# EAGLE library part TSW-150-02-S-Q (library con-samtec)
THROUGH-HOLE .025" SQ POST HEADER Source: Samtec TSW.pdf
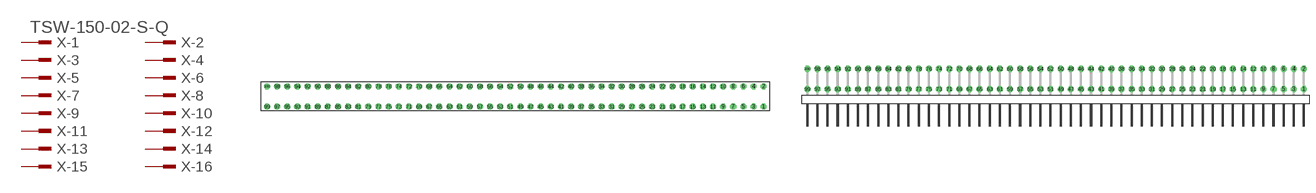
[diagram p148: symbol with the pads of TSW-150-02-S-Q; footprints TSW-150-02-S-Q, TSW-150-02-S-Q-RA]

Designator prefix X; gates -1=MPINV -2=MPIN -3=MPIN -4=MPIN -5=MPIN -6=MPIN -7=MPIN -8=MPIN -9=MPIN -10=MPIN -11=MPIN -12=MPIN -13=MPIN -14=MPIN -15=MPIN -16=MPIN -17=MPIN -18=MPIN -19=MPIN -20=MPIN -21=MPIN -22=MPIN -23=MPIN -24=MPIN -25=MPIN -26=MPIN -27=MPIN -28=MPIN -29=MPIN -30=MPIN -31=MPIN -32=MPIN -33=MPIN -34=MPIN -35=MPIN -36=MPIN -37=MPIN -38=MPIN -39=MPIN -40=MPIN -41=MPIN -42=MPIN -43=MPIN -44=MPIN -45=MPIN -46=MPIN -47=MPIN -48=MPIN -49=MPIN -50=MPIN -51=MPIN -52=MPIN -53=MPIN -54=MPIN -55=MPIN -56=MPIN -57=MPIN -58=MPIN -59=MPIN -60=MPIN -61=MPIN -62=MPIN -63=MPIN -64=MPIN -65=MPIN -66=MPIN -67=MPIN -68=MPIN -69=MPIN -70=MPIN -71=MPIN -72=MPIN -73=MPIN -74=MPIN -75=MPIN -76=MPIN -77=MPIN -78=MPIN -79=MPIN -80=MPIN -81=MPIN -82=MPIN -83=MPIN -84=MPIN -85=MPIN -86=MPIN -87=MPIN -88=MPIN -89=MPIN -90=MPIN -91=MPIN -92=MPIN -93=MPIN -94=MPIN -95=MPIN -96=MPIN -97=MPIN -98=MPIN -99=MPIN -100=MPIN

## TSW-150-02-S-Q (OC_FARNELL: unknown; OC_NEWARK: unknown)  [TSW-150-02-S-Q]
1  -1:1  pas
2  -2:1  pas
3  -3:1  pas
4  -4:1  pas
5  -5:1  pas
6  -6:1  pas
7  -7:1  pas
8  -8:1  pas
9  -9:1  pas
10  -10:1  pas
11  -11:1  pas
12  -12:1  pas
13  -13:1  pas
14  -14:1  pas
15  -15:1  pas
16  -16:1  pas
17  -17:1  pas
18  -18:1  pas
19  -19:1  pas
20  -20:1  pas
21  -21:1  pas
22  -22:1  pas
23  -23:1  pas
24  -24:1  pas
25  -25:1  pas
26  -26:1  pas
27  -27:1  pas
28  -28:1  pas
29  -29:1  pas
30  -30:1  pas
31  -31:1  pas
32  -32:1  pas
33  -33:1  pas
34  -34:1  pas
35  -35:1  pas
36  -36:1  pas
37  -37:1  pas
38  -38:1  pas
39  -39:1  pas
40  -40:1  pas
41  -41:1  pas
42  -42:1  pas
43  -43:1  pas
44  -44:1  pas
45  -45:1  pas
46  -46:1  pas
47  -47:1  pas
48  -48:1  pas
49  -49:1  pas
50  -50:1  pas
51  -51:1  pas
52  -52:1  pas
53  -53:1  pas
54  -54:1  pas
55  -55:1  pas
56  -56:1  pas
57  -57:1  pas
58  -58:1  pas
59  -59:1  pas
60  -60:1  pas
61  -61:1  pas
62  -62:1  pas
63  -63:1  pas
64  -64:1  pas
65  -65:1  pas
66  -66:1  pas
67  -67:1  pas
68  -68:1  pas
69  -69:1  pas
70  -70:1  pas
71  -71:1  pas
72  -72:1  pas
73  -73:1  pas
74  -74:1  pas
75  -75:1  pas
76  -76:1  pas
77  -77:1  pas
78  -78:1  pas
79  -79:1  pas
80  -80:1  pas
81  -81:1  pas
82  -82:1  pas
83  -83:1  pas
84  -84:1  pas
85  -85:1  pas
86  -86:1  pas
87  -87:1  pas
88  -88:1  pas
89  -89:1  pas
90  -90:1  pas
91  -91:1  pas
92  -92:1  pas
93  -93:1  pas
94  -94:1  pas
95  -95:1  pas
96  -96:1  pas
97  -97:1  pas
98  -98:1  pas
99  -99:1  pas
100  -100:1  pas

## TSW-150-02-S-Q-RA (OC_FARNELL: unknown; OC_NEWARK: unknown)  [TSW-150-02-S-Q-RA]
Pads as for TSW-150-02-S-Q

## Footprint TSW-150-02-S-Q (pad centres in mm)
THROUGH-HOLE .025" SQ POST HEADER Source: Samtec TSW.pdf
drill 1 pad 1.5 octagon: 1 62.23,-2.54; 2 62.23,2.54; 3 59.69,-2.54; 4 59.69,2.54; 5 57.15,-2.54; 6 57.15,2.54; 7 54.61,-2.54; 8 54.61,2.54; 9 52.07,-2.54; 10 52.07,2.54; 11 49.53,-2.54; 12 49.53,2.54; 13 46.99,-2.54; 14 46.99,2.54; 15 44.45,-2.54; 16 44.45,2.54; 17 41.91,-2.54; 18 41.91,2.54; 19 39.37,-2.54; 20 39.37,2.54; 21 36.83,-2.54; 22 36.83,2.54; 23 34.29,-2.54; 24 34.29,2.54; 25 31.75,-2.54; 26 31.75,2.54; 27 29.21,-2.54; 28 29.21,2.54; 29 26.67,-2.54; 30 26.67,2.54; 31 24.13,-2.54; 32 24.13,2.54; 33 21.59,-2.54; 34 21.59,2.54; 35 19.05,-2.54; 36 19.05,2.54; 37 16.51,-2.54; 38 16.51,2.54; 39 13.97,-2.54; 40 13.97,2.54; 41 11.43,-2.54; 42 11.43,2.54; 43 8.89,-2.54; 44 8.89,2.54; 45 6.35,-2.54; 46 6.35,2.54; 47 3.81,-2.54; 48 3.81,2.54; 49 1.27,-2.54; 50 1.27,2.54; 51 -1.27,-2.54; 52 -1.27,2.54; 53 -3.81,-2.54; 54 -3.81,2.54; 55 -6.35,-2.54; 56 -6.35,2.54; 57 -8.89,-2.54; 58 -8.89,2.54; 59 -11.43,-2.54; 60 -11.43,2.54; 61 -13.97,-2.54; 62 -13.97,2.54; 63 -16.51,-2.54; 64 -16.51,2.54; 65 -19.05,-2.54; 66 -19.05,2.54; 67 -21.59,-2.54; 68 -21.59,2.54; 69 -24.13,-2.54; 70 -24.13,2.54; 71 -26.67,-2.54; 72 -26.67,2.54; 73 -29.21,-2.54; 74 -29.21,2.54; 75 -31.75,-2.54; 76 -31.75,2.54; 77 -34.29,-2.54; 78 -34.29,2.54; 79 -36.83,-2.54; 80 -36.83,2.54; 81 -39.37,-2.54; 82 -39.37,2.54; 83 -41.91,-2.54; 84 -41.91,2.54; 85 -44.45,-2.54; 86 -44.45,2.54; 87 -46.99,-2.54; 88 -46.99,2.54; 89 -49.53,-2.54; 90 -49.53,2.54; 91 -52.07,-2.54; 92 -52.07,2.54; 93 -54.61,-2.54; 94 -54.61,2.54; 95 -57.15,-2.54; 96 -57.15,2.54; 97 -59.69,-2.54; 98 -59.69,2.54; 99 -62.23,-2.54; 100 -62.23,2.54

## Footprint TSW-150-02-S-Q-RA (pad centres in mm)
THROUGH-HOLE .025" SQ POST HEADER Source: Samtec TSW.pdf
drill 1 pad 1.5 octagon: 1 62.23,1.524; 2 62.23,6.604; 3 59.69,1.524; 4 59.69,6.604; 5 57.15,1.524; 6 57.15,6.604; 7 54.61,1.524; 8 54.61,6.604; 9 52.07,1.524; 10 52.07,6.604; 11 49.53,1.524; 12 49.53,6.604; 13 46.99,1.524; 14 46.99,6.604; 15 44.45,1.524; 16 44.45,6.604; 17 41.91,1.524; 18 41.91,6.604; 19 39.37,1.524; 20 39.37,6.604; 21 36.83,1.524; 22 36.83,6.604; 23 34.29,1.524; 24 34.29,6.604; 25 31.75,1.524; 26 31.75,6.604; 27 29.21,1.524; 28 29.21,6.604; 29 26.67,1.524; 30 26.67,6.604; 31 24.13,1.524; 32 24.13,6.604; 33 21.59,1.524; 34 21.59,6.604; 35 19.05,1.524; 36 19.05,6.604; 37 16.51,1.524; 38 16.51,6.604; 39 13.97,1.524; 40 13.97,6.604; 41 11.43,1.524; 42 11.43,6.604; 43 8.89,1.524; 44 8.89,6.604; 45 6.35,1.524; 46 6.35,6.604; 47 3.81,1.524; 48 3.81,6.604; 49 1.27,1.524; 50 1.27,6.604; 51 -1.27,1.524; 52 -1.27,6.604; 53 -3.81,1.524; 54 -3.81,6.604; 55 -6.35,1.524; 56 -6.35,6.604; 57 -8.89,1.524; 58 -8.89,6.604; 59 -11.43,1.524; 60 -11.43,6.604; 61 -13.97,1.524; 62 -13.97,6.604; 63 -16.51,1.524; 64 -16.51,6.604; 65 -19.05,1.524; 66 -19.05,6.604; 67 -21.59,1.524; 68 -21.59,6.604; 69 -24.13,1.524; 70 -24.13,6.604; 71 -26.67,1.524; 72 -26.67,6.604; 73 -29.21,1.524; 74 -29.21,6.604; 75 -31.75,1.524; 76 -31.75,6.604; 77 -34.29,1.524; 78 -34.29,6.604; 79 -36.83,1.524; 80 -36.83,6.604; 81 -39.37,1.524; 82 -39.37,6.604; 83 -41.91,1.524; 84 -41.91,6.604; 85 -44.45,1.524; 86 -44.45,6.604; 87 -46.99,1.524; 88 -46.99,6.604; 89 -49.53,1.524; 90 -49.53,6.604; 91 -52.07,1.524; 92 -52.07,6.604; 93 -54.61,1.524; 94 -54.61,6.604; 95 -57.15,1.524; 96 -57.15,6.604; 97 -59.69,1.524; 98 -59.69,6.604; 99 -62.23,1.524; 100 -62.23,6.604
